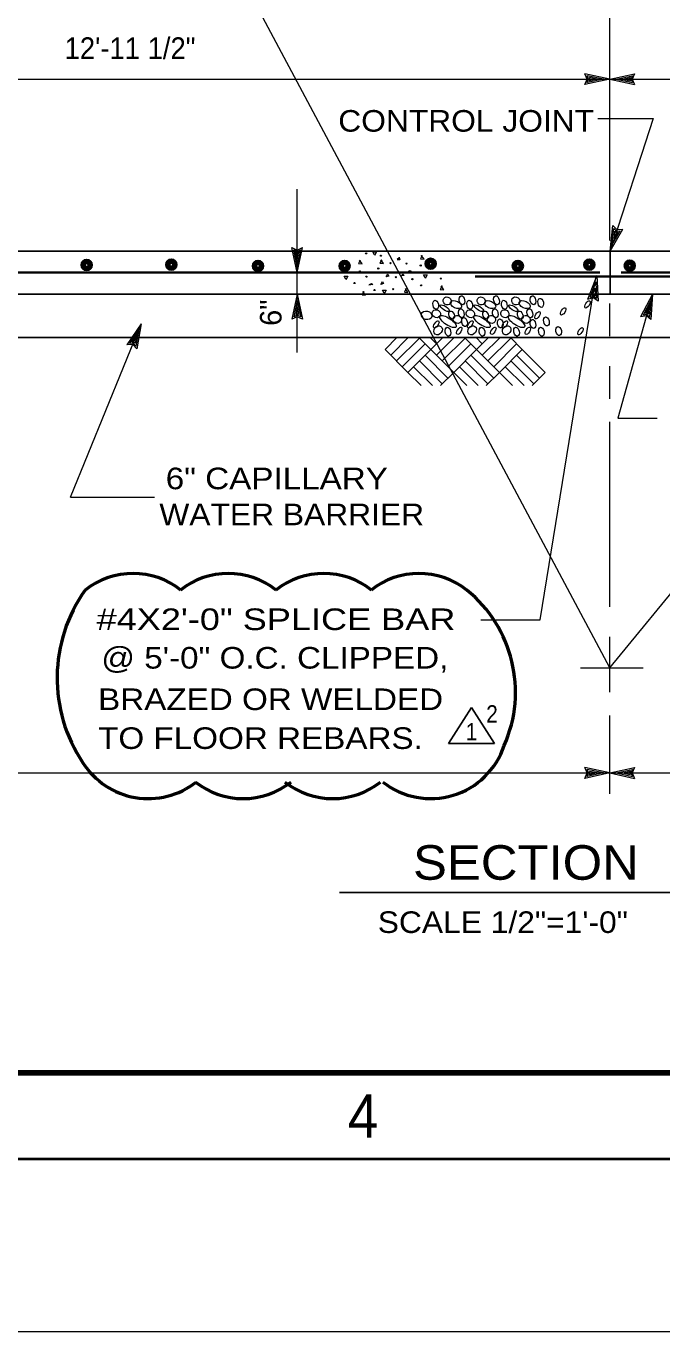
# Model space of a CAD drawing. Extents: x -24.3 to 17.7, y -17.6 to 12.4.
# Drawn here: x -13.29 to -9.61, y -17.61 to -10.05 of the extents above; entities that cross this region are included whole.
import ezdxf
from ezdxf.enums import TextEntityAlignment as Align

# ---------------------------------------------------------------- set-up
doc = ezdxf.new("R2010")
doc.units = 0
doc.header["$LTSCALE"] = 0.05
for name, color, linetype, lineweight in [('1', 7, 'Continuous', 13), ('2', 7, 'Continuous', 13), ('5', 7, 'Continuous', 53)]:
    doc.layers.add(name, color=color, linetype=linetype, lineweight=lineweight)

msp = doc.modelspace()

# ---------------------------------------------------------------- linework, layer by layer
at = {"layer": '1'}
for p, q in [((-9.90869, -11.2926), (-9.90869, -9.7416)), ((-9.90869, -10.3596), (-10.05269, -10.3286)), ((-9.94569, -10.3596), (-10.03969, -10.3396)), ((-10.03069, -10.3596), (-10.03969, -10.3396)), ((-9.98169, -10.3596), (-10.02669, -10.3506)), ((-10.02269, -10.3596), (-10.02669, -10.3506)), ((-9.90869, -10.3596), (-9.76469, -10.3286)), ((-9.87169, -10.3596), (-9.77769, -10.3396)), ((-9.83569, -10.3596), (-9.79069, -10.3496)), ((-9.79069, -10.3496), (-9.79469, -10.3596)), ((-9.77769, -10.3396), (-9.78669, -10.3596)), ((-9.90869, -10.3596), (-10.05269, -10.3906)), ((-9.94569, -10.3596), (-10.03969, -10.3796)), ((-10.03969, -10.3796), (-10.03069, -10.3596)), ((-9.98169, -10.3596), (-10.02669, -10.3696)), ((-10.02669, -10.3696), (-10.02269, -10.3596)), ((-9.90869, -10.3596), (-9.76469, -10.3906)), ((-9.87169, -10.3596), (-9.77769, -10.3796)), ((-9.83569, -10.3596), (-9.79069, -10.3686)), ((-9.79469, -10.3596), (-9.79069, -10.3686)), ((-9.78669, -10.3596), (-9.77769, -10.3796)), ((-9.90669, -11.3546), (-9.83269, -11.2276)), ((-9.89569, -11.3196), (-9.88569, -11.2236)), ((-9.89569, -11.3196), (-9.84769, -11.2366)), ((-9.88569, -11.2236), (-9.86869, -11.2386)), ((-9.88369, -11.2856), (-9.87969, -11.2396)), ((-9.88369, -11.2856), (-9.86169, -11.2456)), ((-9.87969, -11.2396), (-9.87169, -11.2466)), ((-9.87169, -11.2466), (-9.86169, -11.2456)), ((-9.86869, -11.2386), (-9.84769, -11.2366)), ((-11.71769, -11.4786), (-11.74869, -11.3346)), ((-11.71769, -11.4786), (-11.68669, -11.3346)), ((-11.71769, -11.4416), (-11.73769, -11.3476)), ((-11.73769, -11.3476), (-11.71769, -11.3566)), ((-11.71769, -11.4056), (-11.72769, -11.3606)), ((-11.72769, -11.3606), (-11.71769, -11.3646)), ((-11.71769, -11.4416), (-11.69769, -11.3476)), ((-11.71769, -11.3566), (-11.69769, -11.3476)), ((-11.71769, -11.4056), (-11.70869, -11.3606)), ((-11.71769, -11.3646), (-11.70869, -11.3606)), ((-9.98362, -11.49701), (-10.03735, -11.63416)), ((-9.98957, -11.53353), (-10.02441, -11.62309)), ((-9.98957, -11.53353), (-9.98493, -11.62952)), ((-9.98362, -11.49701), (-9.97616, -11.64412)), ((-11.71769, -11.6046), (-11.74869, -11.7486)), ((-11.71769, -11.6046), (-11.68669, -11.7486)), ((-11.71769, -11.9426), (-11.71769, -11.6046)), ((-10.00322, -11.61743), (-10.02441, -11.62309)), ((-9.99535, -11.56906), (-10.01146, -11.61203)), ((-10.00194, -11.60953), (-10.01146, -11.61203)), ((-9.98493, -11.62952), (-10.00322, -11.61743)), ((-9.99271, -11.61508), (-10.00194, -11.60953)), ((-9.99535, -11.56906), (-9.99271, -11.61508)), ((-9.66169, -11.6046), (-9.73069, -11.7346)), ((-9.66169, -11.6046), (-9.67069, -11.7516)), ((-11.71769, -11.6416), (-11.73769, -11.7356)), ((-11.71769, -11.6776), (-11.72669, -11.7226)), ((-11.71769, -11.6416), (-11.69769, -11.7356)), ((-11.71769, -11.6776), (-11.70769, -11.7226)), ((-9.90869, -11.8476), (-9.90869, -11.6586)), ((-9.67169, -11.6406), (-9.71569, -11.7256)), ((-9.68169, -11.6746), (-9.70169, -11.7156)), ((-9.69269, -11.7146), (-9.70169, -11.7156)), ((-9.68369, -11.7206), (-9.69269, -11.7146)), ((-9.68169, -11.6746), (-9.68369, -11.7206)), ((-9.67169, -11.6406), (-9.67769, -11.7366)), ((-12.62069, -11.7756), (-12.70369, -11.8976)), ((-11.71769, -11.7266), (-11.73769, -11.7356)), ((-11.71769, -11.7186), (-11.72669, -11.7226)), ((-11.70769, -11.7226), (-11.71769, -11.7186)), ((-11.69769, -11.7356), (-11.71769, -11.7266)), ((-9.69469, -11.7226), (-9.71569, -11.7256)), ((-9.67769, -11.7366), (-9.69469, -11.7226)), ((-12.63469, -11.8096), (-12.68869, -11.8896)), ((-12.64869, -11.8436), (-12.67369, -11.8816)), ((-12.64869, -11.8436), (-12.65569, -11.8886)), ((-12.63469, -11.8096), (-12.65169, -11.9046)), ((-11.20969, -11.9246), (-11.13869, -11.8536)), ((-11.17669, -11.9576), (-11.07269, -11.8536)), ((-11.14369, -11.9906), (-11.01069, -11.8586)), ((-10.94469, -11.9246), (-11.01569, -11.8536)), ((-10.91169, -11.8916), (-10.94969, -11.8536)), ((-10.94469, -11.9246), (-10.87369, -11.8536)), ((-10.94469, -11.9246), (-10.87369, -11.8536)), ((-10.91169, -11.9576), (-10.80769, -11.8536)), ((-10.87869, -11.8586), (-10.88369, -11.8536)), ((-10.87869, -11.9906), (-10.74569, -11.8586)), ((-10.67969, -11.9246), (-10.75069, -11.8536)), ((-10.64669, -11.8916), (-10.68469, -11.8536)), ((-10.67969, -11.9246), (-10.60869, -11.8536)), ((-10.64669, -11.9576), (-10.54169, -11.8536)), ((-10.61369, -11.8586), (-10.61769, -11.8536)), ((-10.61369, -11.9906), (-10.48069, -11.8586)), ((-10.41469, -11.9246), (-10.48569, -11.8536)), ((-12.66669, -11.8886), (-12.68869, -11.8896)), ((-12.66369, -11.8816), (-12.67369, -11.8816)), ((-12.65169, -11.9046), (-12.66669, -11.8886)), ((-12.65569, -11.8886), (-12.66369, -11.8816)), ((-11.11069, -12.0246), (-10.97769, -11.8916)), ((-11.07769, -12.0576), (-10.94469, -11.9246)), ((-10.81169, -12.0576), (-10.94469, -11.9246)), ((-10.84569, -12.0246), (-10.71269, -11.8916)), ((-10.81169, -12.0576), (-10.67969, -11.9246)), ((-10.57969, -12.0246), (-10.44769, -11.8916)), ((-10.54669, -12.0576), (-10.41469, -11.9246)), ((-10.28169, -12.0576), (-10.41469, -11.9246)), ((-10.87869, -12.1236), (-11.01069, -11.9906)), ((-10.84569, -12.0906), (-10.97769, -11.9576)), ((-10.61369, -12.1236), (-10.74569, -11.9906)), ((-10.57969, -12.0906), (-10.71269, -11.9576)), ((-10.34769, -12.1236), (-10.48069, -11.9906)), ((-10.31469, -12.0906), (-10.44769, -11.9576)), ((-10.93469, -12.1336), (-11.04469, -12.0246)), ((-10.88869, -12.1336), (-10.81169, -12.0576)), ((-10.73569, -12.1336), (-10.81169, -12.0576)), ((-10.66969, -12.1336), (-10.77869, -12.0246)), ((-10.62369, -12.1336), (-10.54669, -12.0576)), ((-10.40369, -12.1336), (-10.51369, -12.0246)), ((-10.35869, -12.1336), (-10.28169, -12.0576)), ((-9.90869, -12.2096), (-9.90869, -12.0216)), ((-9.90869, -13.4136), (-9.90869, -12.3426)), ((-9.90869, -13.7666), (-8.82569, -12.4476)), ((-13.03048, -12.77991), (-12.54403, -12.77991)), ((-9.90869, -13.9076), (-9.90869, -13.5876)), ((-10.07769, -13.7666), (-9.71569, -13.7666)), ((-9.90869, -14.4956), (-9.90869, -14.0436)), ((-9.90869, -14.3756), (-10.05269, -14.3446)), ((-9.94569, -14.3756), (-10.03969, -14.3556)), ((-10.03069, -14.3756), (-10.03969, -14.3556)), ((-9.90869, -14.3756), (-9.76469, -14.3446)), ((-9.87169, -14.3756), (-9.77769, -14.3556)), ((-9.77769, -14.3556), (-9.78669, -14.3756)), ((-9.90869, -14.3756), (-10.05269, -14.4066)), ((-9.94569, -14.3756), (-10.03969, -14.3956)), ((-10.03969, -14.3956), (-10.03069, -14.3756)), ((-9.98169, -14.3756), (-10.02669, -14.3666)), ((-10.02269, -14.3756), (-10.02669, -14.3666)), ((-9.98169, -14.3756), (-10.02669, -14.3856)), ((-10.02669, -14.3856), (-10.02269, -14.3756)), ((-9.90869, -14.3756), (-9.76469, -14.4066)), ((-9.87169, -14.3756), (-9.77769, -14.3956)), ((-9.83569, -14.3756), (-9.79069, -14.3656)), ((-9.83569, -14.3756), (-9.79069, -14.3846)), ((-9.79069, -14.3656), (-9.79469, -14.3756)), ((-9.79469, -14.3756), (-9.79069, -14.3846)), ((-9.78669, -14.3756), (-9.77769, -14.3956)), ((17.65731, -17.6106), (-24.34269, -17.6106))]:
    msp.add_line(p, q, dxfattribs=at)
at = {"layer": '1', "lineweight": 25}
for p, q in [((-16.07569, -11.3546), (-3.74269, -11.3546)), ((-9.90669, -11.6046), (-9.90669, -11.3546)), ((-16.07569, -11.6046), (-3.74269, -11.6046)), ((-16.07569, -11.8546), (-3.74269, -11.8546)), ((-10.84243, -14.20544), (-10.70943, -13.99644)), ((-10.57643, -14.20544), (-10.70943, -13.99644)), ((-10.84243, -14.20544), (-10.57643, -14.20544)), ((-11.47369, -15.0666), (-8.76469, -15.0666))]:
    msp.add_line(p, q, dxfattribs=at)
at = {"layer": '1', "lineweight": 35}
for p, q in [((-16.13916, -11.4796), (-9.96569, -11.4796)), ((-9.84169, -11.4796), (-3.67137, -11.4796)), ((-10.68781, -11.50146), (-9.09967, -11.50146))]:
    msp.add_line(p, q, dxfattribs=at)
at = {"layer": '1', "lineweight": 40}
msp.add_lwpolyline([(-23.34269, -16.6106), (-23.34269, 11.3894), (16.65731, 11.3894), (16.65731, -16.6106)], close=True, dxfattribs=at)
at = {"layer": '1', "lineweight": 90}
msp.add_lwpolyline([(-21.84269, 10.8894), (16.15731, 10.8894), (16.15731, -16.1106), (-21.84269, -16.1106)], close=True, dxfattribs=at)
at = {"layer": '1'}
for points in [[(-9.90869, -13.7666), (-14.47869, -5.2016), (-14.38369, -5.3136)], [(-10.05269, -10.3906), (-10.03869, -10.3596), (-10.05269, -10.3286)], [(-9.76469, -10.3286), (-9.77869, -10.3596), (-9.76469, -10.3906)], [(-16.38769, -10.3596), (-9.90869, -10.3596), (-3.42969, -10.3596), (-3.57369, -10.3906)], [(-9.9767, -10.5866), (-9.65769, -10.5866), (-9.90669, -11.3546), (-9.89169, -11.2076)], [(-11.71769, -11.6046), (-11.71769, -11.4786), (-11.71769, -10.9966)], [(-9.89169, -11.2076), (-9.86669, -11.2306), (-9.83269, -11.2276)], [(-11.74869, -11.3346), (-11.71769, -11.3486), (-11.68669, -11.3346)], [(-10.65407, -13.48858), (-10.31177, -13.48858), (-9.98949, -11.50824)], [(-9.97616, -11.64412), (-10.00451, -11.62532), (-10.03735, -11.63416)], [(-9.66169, -11.6046), (-9.86169, -12.3216), (-9.63369, -12.3216)], [(-13.03048, -12.77991), (-12.62069, -11.7756), (-12.64669, -11.9206)], [(-11.68669, -11.7486), (-11.71769, -11.7346), (-11.74869, -11.7486)], [(-9.67069, -11.7516), (-9.69669, -11.7296), (-9.73069, -11.7346)], [(-10.47069, -12.1336), (-10.67969, -11.9246), (-10.60869, -11.8536)], [(-12.64669, -11.9206), (-12.66969, -11.8956), (-12.70369, -11.8976)], [(-11.00069, -12.1336), (-11.07769, -12.0576), (-11.20969, -11.9246)], [(-10.05269, -14.4066), (-10.03869, -14.3756), (-10.05269, -14.3446)], [(-9.76469, -14.3446), (-9.77869, -14.3756), (-9.76469, -14.4066)], [(-16.07669, -14.3756), (-9.90869, -14.3756), (-3.74269, -14.3756)]]:
    msp.add_lwpolyline(points, dxfattribs=at)
at = {"layer": '1', "lineweight": 25}
for centre, radius in [((-12.93659, -11.43513), 0.0319), ((-12.93659, -11.43513), 0.02658), ((-12.44661, -11.43313), 0.0319), ((-12.44661, -11.43313), 0.02658), ((-12.44661, -11.43313), 0.02215), ((-11.94462, -11.44113), 0.0319), ((-11.44364, -11.44113), 0.0319), ((-10.94565, -11.42813), 0.0319), ((-10.94565, -11.42813), 0.02658), ((-10.94565, -11.42813), 0.02215), ((-10.94565, -11.42813), 0.01846), ((-10.44067, -11.44113), 0.0319), ((-10.02669, -11.43313), 0.0319), ((-10.02669, -11.43313), 0.02658), ((-10.02669, -11.43313), 0.02215), ((-9.79269, -11.43913), 0.0319), ((-9.79269, -11.43913), 0.02658), ((-12.93659, -11.43513), 0.02215), ((-12.93659, -11.43513), 0.01846), ((-12.93659, -11.43513), 0.01538), ((-12.93659, -11.43513), 0.01282), ((-12.93659, -11.43513), 0.01068), ((-12.93659, -11.43513), 0.0089), ((-12.44661, -11.43313), 0.01846), ((-12.44661, -11.43313), 0.01538), ((-12.44661, -11.43313), 0.01282), ((-12.44661, -11.43313), 0.01068), ((-12.44661, -11.43313), 0.0089), ((-11.94462, -11.44113), 0.02658), ((-11.94462, -11.44113), 0.02215), ((-11.94462, -11.44113), 0.01846), ((-11.94462, -11.44113), 0.01538), ((-11.94462, -11.44113), 0.01282), ((-11.94462, -11.44113), 0.01068), ((-11.94462, -11.44113), 0.0089), ((-11.44364, -11.44113), 0.02658), ((-11.44364, -11.44113), 0.02215), ((-11.44364, -11.44113), 0.01846), ((-11.44364, -11.44113), 0.01538), ((-11.44364, -11.44113), 0.01282), ((-11.44364, -11.44113), 0.01068), ((-11.44364, -11.44113), 0.0089), ((-10.94565, -11.42813), 0.01538), ((-10.94565, -11.42813), 0.01282), ((-10.94565, -11.42813), 0.01068), ((-10.94565, -11.42813), 0.0089), ((-10.44067, -11.44113), 0.02658), ((-10.44067, -11.44113), 0.02215), ((-10.44067, -11.44113), 0.01846), ((-10.44067, -11.44113), 0.01538), ((-10.44067, -11.44113), 0.01282), ((-10.44067, -11.44113), 0.01068), ((-10.44067, -11.44113), 0.0089), ((-10.02669, -11.43313), 0.01846), ((-10.02669, -11.43313), 0.01538), ((-10.02669, -11.43313), 0.01282), ((-10.02669, -11.43313), 0.01068), ((-10.02669, -11.43313), 0.0089), ((-9.79269, -11.43913), 0.02215), ((-9.79269, -11.43913), 0.01846), ((-9.79269, -11.43913), 0.01538), ((-9.79269, -11.43913), 0.01282), ((-9.79269, -11.43913), 0.01068), ((-9.79269, -11.43913), 0.0089)]:
    msp.add_circle(centre, radius, dxfattribs=at)
at = {"layer": '1', "lineweight": 53}
for centre, radius, start, end in [((-12.22937, -13.82631), 0.87852, 144.52737, 213.95759), ((-11.21501, -13.90801), 0.76087, 336.11964, 51.02555)]:
    msp.add_arc(centre, radius, start, end, dxfattribs=at)
at = {"layer": '1'}
for centre, major_axis, ratio in [((-10.91619, -11.6656), (-0.0055, 0.026), 0.599528), ((-10.84969, -11.6431), (-0.02021, 0.0142), 0.915279), ((-10.79819, -11.6646), (-0.0315, 0.015), 0.562188), ((-10.76419, -11.6396), (-0.0055, 0.026), 0.599528), ((-10.71919, -11.6656), (-0.0055, 0.026), 0.599528), ((-10.65269, -11.6431), (-0.02021, 0.0142), 0.915279), ((-10.60119, -11.6646), (-0.0315, 0.015), 0.562188), ((-10.56419, -11.6396), (-0.0055, 0.026), 0.599528), ((-10.51919, -11.6656), (-0.0055, 0.026), 0.599528), ((-10.45269, -11.6431), (-0.02021, 0.0142), 0.915279), ((-10.40119, -11.6646), (-0.0315, 0.015), 0.562188), ((-10.35319, -11.6396), (-0.0055, 0.026), 0.599528), ((-10.30819, -11.6546), (-0.0055, 0.026), 0.599528), ((-10.96919, -11.7266), (-0.03038, 0.00696), 0.790099), ((-10.91269, -11.7171), (-0.02021, 0.0142), 0.915279), ((-10.86369, -11.6856), (-0.026, 0.017), 0.365968), ((-10.82369, -11.7251), (-0.009, 0.0225), 0.615421), ((-10.76819, -11.7146), (-0.0055, 0.026), 0.599528), ((-10.71569, -11.7171), (-0.02021, 0.0142), 0.915279), ((-10.66669, -11.6856), (-0.026, 0.017), 0.365968), ((-10.62669, -11.7251), (-0.009, 0.0225), 0.615421), ((-10.57119, -11.7146), (-0.0055, 0.026), 0.599528), ((-10.51569, -11.7171), (-0.02021, 0.0142), 0.915279), ((-10.46669, -11.6856), (-0.026, 0.017), 0.365968), ((-10.42669, -11.7251), (-0.009, 0.0225), 0.615421), ((-10.37119, -11.7146), (-0.0055, 0.026), 0.599528), ((-10.32669, -11.7261), (0.013, 0.0205), 0.445558), ((-10.17869, -11.7041), (0.013, 0.0205), 0.445558), ((-10.03769, -11.6631), (0.013, 0.0205), 0.445558), ((-10.91269, -11.7791), (0.013, 0.0205), 0.445558), ((-10.90219, -11.8131), (0.0165, 0.0225), 0.822116), ((-10.84469, -11.7631), (-0.04615, 0.03077), 0.357541), ((-10.79069, -11.7501), (-0.02021, 0.0142), 0.915279), ((-10.74919, -11.7656), (-0.0055, 0.026), 0.599528), ((-10.71569, -11.7791), (0.013, 0.0205), 0.445558), ((-10.70519, -11.8131), (0.0165, 0.0225), 0.822116), ((-10.64769, -11.7631), (-0.04615, 0.03077), 0.357541), ((-10.59369, -11.7501), (-0.02021, 0.0142), 0.915279), ((-10.54219, -11.7736), (-0.0055, 0.026), 0.599528), ((-10.51569, -11.7791), (0.013, 0.0205), 0.445558), ((-10.50519, -11.8131), (0.0165, 0.0225), 0.822116), ((-10.44769, -11.7631), (-0.04615, 0.03077), 0.357541), ((-10.39369, -11.7501), (-0.02021, 0.0142), 0.915279), ((-10.35319, -11.7766), (-0.0055, 0.026), 0.599528), ((-10.27519, -11.7616), (-0.0055, 0.026), 0.599528), ((-10.20419, -11.8176), (-0.0055, 0.026), 0.599528), ((-10.84519, -11.8216), (-0.0055, 0.026), 0.599528), ((-10.77969, -11.8161), (0.013, 0.0205), 0.445558), ((-10.64819, -11.8216), (-0.0055, 0.026), 0.599528), ((-10.58269, -11.8161), (0.013, 0.0205), 0.445558), ((-10.44819, -11.8216), (-0.0055, 0.026), 0.599528), ((-10.38269, -11.8161), (0.013, 0.0205), 0.445558), ((-10.30419, -11.8216), (-0.0055, 0.026), 0.599528), ((-10.07869, -11.8191), (0.013, 0.0205), 0.445558)]:
    msp.add_ellipse(centre, major_axis=major_axis, ratio=ratio, dxfattribs=at)
at = {"layer": '2'}
msp.add_line((-11.13869, -11.4016), (-11.12769, -11.3916), dxfattribs=at)
for points in [[(-11.35269, -11.4066), (-11.36269, -11.4266), (-11.34269, -11.4286), (-11.35769, -11.4066)], [(-11.27069, -11.3766), (-11.28069, -11.3596), (-11.25869, -11.3596), (-11.27069, -11.3796)], [(-11.22869, -11.4046), (-11.23869, -11.4246), (-11.21769, -11.4266), (-11.23369, -11.4046)], [(-11.12769, -11.3896), (-11.12369, -11.4046), (-11.13869, -11.4046)], [(-10.99469, -11.3796), (-11.00469, -11.3996), (-10.98369, -11.4016), (-10.99969, -11.3796)], [(-11.11369, -11.4956), (-11.10669, -11.4876), (-11.09869, -11.4956), (-11.11169, -11.4976)], [(-11.07369, -11.4706), (-11.06369, -11.4666), (-11.05869, -11.4776), (-11.07369, -11.4726)], [(-11.43669, -11.5176), (-11.44669, -11.5006), (-11.42469, -11.5006), (-11.43669, -11.5216)], [(-11.29869, -11.5476), (-11.28869, -11.5416), (-11.28069, -11.5476), (-11.30369, -11.5516)], [(-10.97769, -11.5096), (-10.98769, -11.4926), (-10.96569, -11.4926), (-10.97769, -11.5126)], [(-10.87969, -11.5566), (-10.88969, -11.5766), (-10.86969, -11.5786), (-10.88469, -11.5566)], [(-11.33269, -11.5886), (-11.34269, -11.6086), (-11.32269, -11.6106), (-11.33769, -11.5886)], [(-11.21469, -11.5986), (-11.22469, -11.5816), (-11.20269, -11.5816), (-11.21469, -11.6016)], [(-11.08669, -11.5716), (-11.09669, -11.5916), (-11.07669, -11.5936), (-11.09169, -11.5716)]]:
    msp.add_lwpolyline(points, dxfattribs=at)
for points in [[(-11.20369, -11.5046), (-11.19369, -11.4876), (-11.18769, -11.4996)], [(-11.23369, -11.5476), (-11.22369, -11.5306), (-11.21769, -11.5426)]]:
    msp.add_lwpolyline(points, close=True, dxfattribs=at)
for centre in [(-11.31885, -11.36802), (-11.23335, -11.38152), (-11.43535, -11.42152), (-11.35585, -11.47201), (-11.24835, -11.45551), (-11.17785, -11.42502), (-11.08536, -11.42702), (-11.00286, -11.43852), (-11.38635, -11.53951), (-11.31735, -11.50251), (-11.14736, -11.50601), (-11.05136, -11.51751), (-11.00086, -11.55301), (-10.88636, -11.51401), (-11.27035, -11.58001), (-11.16235, -11.57501)]:
    msp.add_circle(centre, 0.00325, dxfattribs=at)
at = {"layer": '5'}
for centre, start, end in [((-12.66783, -13.66869), 51.81631, 128.18369), ((-12.11697, -13.66869), 51.81631, 128.18369), ((-11.5643, -13.66869), 51.81631, 128.18369), ((-11.01344, -13.66869), 51.81631, 128.18369), ((-10.94489, -14.07591), 231.81631, 341.77786), ((-12.58038, -14.07591), 212.55495, 308.18369), ((-12.03062, -14.07591), 231.81631, 308.18369), ((-11.51245, -14.07591), 231.81631, 308.18369)]:
    msp.add_arc(centre, 0.44809, start, end, dxfattribs=at)

# ---------------------------------------------------------------- texts
at = {"layer": '1'}
for s, height, width, p in [('12\'-11 1/2"', 0.125, 0.95, (-12.68569, -10.2426)), ('6" CAPILLARY', 0.125, 1.15, (-11.83604, -12.7332)), ('WATER BARRIER', 0.125, 1.1, (-11.74979, -12.9416)), ('2', 0.1, 0.9, (-10.59009, -14.08344)), ('1', 0.1, 0.9, (-10.70909, -14.18644)), ('SECTION', 0.2, 1.1, (-10.39369, -14.9936)), ('4', 0.25, 0.95, (-11.33619, -16.4856))]:
    msp.add_text(s, height=height, dxfattribs=dict(at, width=width)).set_placement(p, align=Align.CENTER)
at = {"layer": '1', "width": 1.1}
msp.add_text('CONTROL JOINT', height=0.125, dxfattribs=at).set_placement((-9.99911, -10.6636), align=Align.RIGHT)
at = {"layer": '1'}
msp.add_text('6"', height=0.125, rotation=90, dxfattribs=at).set_placement((-11.80869, -11.7876))
for s, width, p in [('#4X2\'-0" SPLICE BAR', 1.25, (-12.87911, -13.54833)), ('@ 5\'-0" O.C. CLIPPED,', 1.15, (-12.85211, -13.77133)), ('BRAZED OR WELDED', 1.15, (-12.87057, -14.01136)), ('TO FLOOR REBARS.', 1.15, (-12.87057, -14.23637)), ('SCALE 1/2"=1\'-0"', 1.1, (-11.25169, -15.3016))]:
    msp.add_text(s, height=0.125, dxfattribs=dict(at, width=width)).set_placement(p)

doc.saveas('drawing.dxf')
